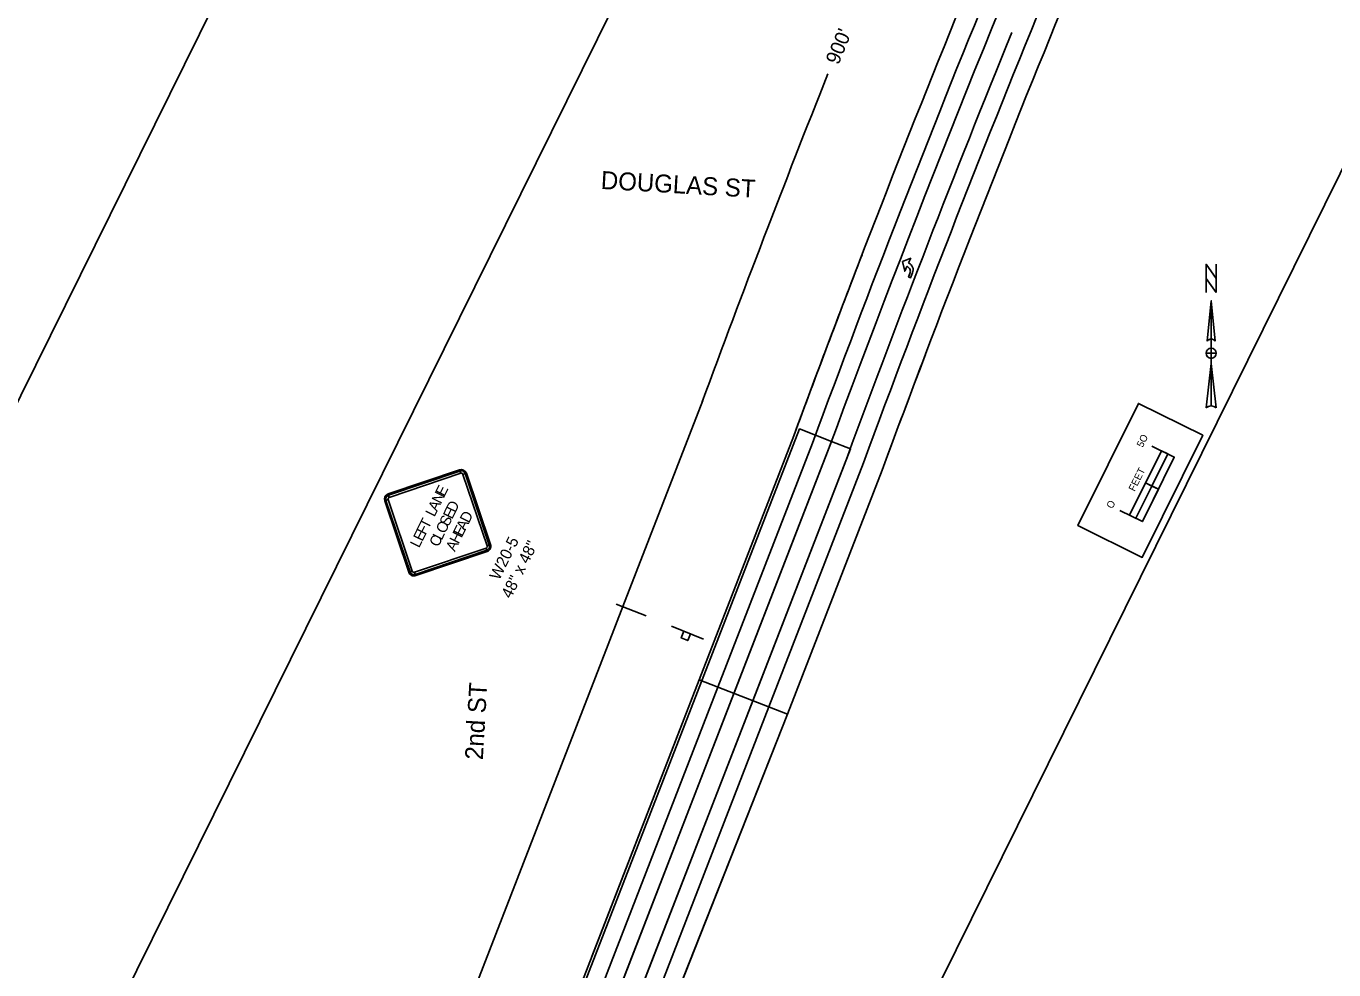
# Model space of a CAD drawing. Extents: x 14104283 to 14129344, y 8637090 to 8673339.
# Drawn here: x 14119504 to 14120414, y 8670301 to 8670958 of the extents above; entities that cross this region are included whole.
import ezdxf

# ---------------------------------------------------------------- set-up
doc = ezdxf.new("R2010")
doc.units = 0
for name, color, linetype in [('Cell', 7, 'Continuous'), ('Default', 7, 'Continuous'), ('dsnCellsNorthArrow', 7, 'Continuous'), ('dsnCellsScaleBlock', 7, 'Continuous'), ('dsnNonPlotable', 7, 'Continuous'), ('dsnPaintExistingBrokenLaneLineWhite', 7, 'Continuous'), ('dsnPaintExistingEdgeLineRightWhite', 7, 'Continuous'), ('dsnPaintExistingNoPassingYellow', 7, 'Continuous'), ('dsnPaintExistingSymbolWhite', 7, 'Continuous'), ('dsnShadingPaved', 7, 'Continuous'), ('dsnStdLabel', 7, 'Continuous'), ('dsnTextOverlapEven', 7, 'Continuous'), ('dsnTextOverlapOdd', 7, 'Continuous')]:
    doc.layers.add(name, color=color, linetype=linetype)

msp = doc.modelspace()

# ---------------------------------------------------------------- linework, layer by layer
at = {"layer": 'Cell'}
for p, q in [((14120117.97, 8670793.22), (14120118.14, 8670793.15)), ((14120117.15, 8670790.72), (14120116.85, 8670790.83)), ((14119805.41, 8670649.2), (14119755.68, 8670632.38)), ((14119805.71, 8670648.31), (14119806.21, 8670646.84)), ((14119807.8, 8670646.05), (14119809.28, 8670646.55)), ((14119826.99, 8670597.12), (14119810.16, 8670646.85)), ((14119753.33, 8670627.62), (14119770.15, 8670577.89)), ((14119754.22, 8670627.93), (14119755.7, 8670628.43)), ((14119756.48, 8670630.01), (14119755.98, 8670631.49)), ((14119774.91, 8670575.54), (14119824.64, 8670592.37)), ((14119823.84, 8670594.74), (14119824.34, 8670593.26)), ((14119826.1, 8670596.82), (14119824.62, 8670596.32)), ((14119772.52, 8670578.69), (14119771.04, 8670578.19)), ((14119774.61, 8670576.43), (14119774.11, 8670577.91)), ((14119952.85, 8670540.35), (14119975.12, 8670531.39))]:
    msp.add_line(p, q, dxfattribs=at)
for points in [[(14120113.8, 8670794.36), (14120119.54, 8670796.55), (14120117.97, 8670793.22)], [(14120113.8, 8670794.36), (14120119.54, 8670796.55), (14120117.97, 8670793.22)], [(14120116.85, 8670790.83), (14120115.29, 8670787.5), (14120113.8, 8670794.36)], [(14120116.85, 8670790.83), (14120115.29, 8670787.5), (14120113.8, 8670794.36)], [(14120117.97, 8670793.22), (14120118.14, 8670793.15)], [(14120117.15, 8670790.72), (14120116.85, 8670790.83)], [(14120120.76, 8670786.39), (14120119.36, 8670782.99), (14120117.98, 8670783.56), (14120118.97, 8670785.99)], [(14120120.76, 8670786.39), (14120119.36, 8670782.99), (14120117.98, 8670783.56), (14120118.97, 8670785.99)], [(14119966.14, 8670534.92), (14119961.58, 8670536.75), (14119959.75, 8670532.19), (14119964.31, 8670530.36), (14119966.14, 8670534.92)]]:
    msp.add_lwpolyline(points, dxfattribs=at)
for points in [[(14119805.71, 8670648.31), (14119755.98, 8670631.49), (14119756.48, 8670630.01), (14119806.21, 8670646.84), (14119805.71, 8670648.31)], [(14119826.1, 8670596.82), (14119809.28, 8670646.55), (14119807.8, 8670646.05), (14119824.62, 8670596.32), (14119826.1, 8670596.82)], [(14119754.22, 8670627.93), (14119771.04, 8670578.19), (14119772.52, 8670578.69), (14119755.7, 8670628.43), (14119754.22, 8670627.93)], [(14119774.61, 8670576.43), (14119824.34, 8670593.26), (14119823.84, 8670594.74), (14119774.11, 8670577.91), (14119774.61, 8670576.43)], [(14119966.14, 8670534.92), (14119961.58, 8670536.75), (14119959.75, 8670532.19), (14119964.31, 8670530.36)]]:
    msp.add_lwpolyline(points, close=True, dxfattribs=at)
for centre, radius, start, end in [((14119806.61, 8670645.65), 3.75, 18.69133, 108.69097), ((14119806.61, 8670645.65), 2.81, 18.69133, 108.69097), ((14119806.61, 8670645.65), 1.25, 18.69133, 108.69097), ((14119756.88, 8670628.83), 3.75, 108.69116, 198.69091), ((14119756.88, 8670628.83), 2.81, 108.69116, 198.69091), ((14119756.88, 8670628.83), 1.25, 108.69116, 198.69091), ((14119823.44, 8670595.92), 1.25, 288.69112, 18.69133), ((14119823.44, 8670595.92), 2.81, 288.69112, 18.69133), ((14119823.44, 8670595.92), 3.75, 288.69112, 18.69133), ((14119773.71, 8670579.1), 3.75, 198.69091, 288.69112), ((14119773.71, 8670579.1), 2.81, 198.69091, 288.69112), ((14119773.71, 8670579.1), 1.25, 198.69091, 288.69112)]:
    msp.add_arc(centre, radius, start, end, dxfattribs=at)
for centre, major_axis in [((14120116.15, 8670788.28), (-2, -4.86)), ((14120116.15, 8670788.28), (-2, -4.86)), ((14120115.75, 8670787.31), (-1.4, -3.4)), ((14120115.75, 8670787.31), (-1.4, -3.4))]:
    msp.add_ellipse(centre, major_axis=major_axis, ratio=0.9474, start_param=1.570796, end_param=3.141593, dxfattribs=at)
at = {"layer": 'Default'}
for p, q in [((14119972.19, 8670502.91), (14120038.08, 8670672.89)), ((14120099.62, 8670649.04), (14120033.72, 8670479.06)), ((14120033.72, 8670479.06), (14119972.19, 8670502.91))]:
    msp.add_line(p, q, dxfattribs=at)
msp.add_lwpolyline([(14119861.3, 8670216.88), (14119920.98, 8670193.76), (14120033.72, 8670479.06), (14119972.19, 8670502.91)], close=True, dxfattribs=at)
for centre in [(14129121.85, 8667322.17), (14129183.39, 8667298.31)]:
    msp.add_arc(centre, 9682.06, 155.679047, 159.752527, dxfattribs=at)
at = {"layer": 'dsnCellsNorthArrow'}
for p, q in [((14120328.64, 8670766.96), (14120331.45, 8670738.79)), ((14120328.64, 8670766.96), (14120328.64, 8670693.71)), ((14120325.82, 8670738.79), (14120325.82, 8670738.79)), ((14120325.93, 8670739.05), (14120326.45, 8670739.63)), ((14120325.12, 8670692.3), (14120328.64, 8670723.29)), ((14120328.64, 8670726.82), (14120328.64, 8670726.81))]:
    msp.add_line(p, q, dxfattribs=at)
msp.add_lwpolyline([(14120332.16, 8670772.59), (14120325.12, 8670782.45), (14120325.12, 8670792.31), (14120332.16, 8670782.45)], close=True, dxfattribs=at)
for points in [[(14120325.12, 8670772.59), (14120325.12, 8670792.31), (14120332.16, 8670782.45), (14120332.16, 8670792.31)], [(14120325.82, 8670738.79), (14120328.64, 8670766.96), (14120328.64, 8670740.2)], [(14120328.64, 8670726.81), (14120328.64, 8670730.34), (14120325.12, 8670730.34)], [(14120332.16, 8670730.34), (14120328.64, 8670730.34), (14120328.64, 8670733.86)], [(14120328.64, 8670693.71), (14120328.64, 8670723.29), (14120332.16, 8670692.31)]]:
    msp.add_lwpolyline(points, dxfattribs=at)
for centre, radius, start, end in [((14120328.64, 8670736.67), 3.52, 90.02039, 143.12574), ((14120328.64, 8670736.68), 3.52, 36.84806, 90.02184), ((14120328.64, 8670730.34), 3.52, 90, 180), ((14120328.64, 8670730.34), 3.52, 180, 270), ((14120328.64, 8670730.34), 3.52, 0, 90), ((14120328.64, 8670730.34), 3.52, 270, 360), ((14120328.64, 8670688.61), 5.1, 89.98939, 133.61895), ((14120328.64, 8670688.61), 5.11, 46.40206, 90.00064)]:
    msp.add_arc(centre, radius, start, end, dxfattribs=at)
at = {"layer": 'dsnCellsScaleBlock'}
msp.add_line((14120291.87, 8670635.63), (14120282.9, 8670640.06), dxfattribs=at)
msp.add_line((14120291.87, 8670635.63), (14120282.9, 8670640.06), dxfattribs=at)
for points in [[(14120235.85, 8670610.33), (14120277.96, 8670695.49), (14120322.78, 8670673.33), (14120280.67, 8670588.17)], [(14120280.67, 8670588.17), (14120235.85, 8670610.33), (14120277.96, 8670695.49), (14120322.78, 8670673.33)], [(14120287.35, 8670637.86), (14120298.43, 8670660.27), (14120293.98, 8670662.47), (14120282.9, 8670640.06)], [(14120280.78, 8670613.22), (14120291.87, 8670635.63), (14120287.35, 8670637.86), (14120276.27, 8670615.45)]]:
    msp.add_lwpolyline(points, close=True, dxfattribs=at)
for points in [[(14120265.1, 8670620.97), (14120280.78, 8670613.22), (14120302.95, 8670658.04), (14120287.26, 8670665.79)], [(14120271.82, 8670617.65), (14120293.98, 8670662.47)]]:
    msp.add_lwpolyline(points, dxfattribs=at)
at = {"layer": 'dsnNonPlotable'}
for points in [[(14119282.05, 8670260.59), (14119976.78, 8671665.73), (14120882.16, 8671218.09), (14120187.43, 8669812.95)], [(14119506.15, 8670149.79), (14120200.88, 8671554.92), (14120653.57, 8671331.1), (14119958.84, 8669925.97)]]:
    msp.add_lwpolyline(points, close=True, dxfattribs=at)
at = {"layer": 'dsnPaintExistingBrokenLaneLineWhite'}
for p, q in [((14119985.24, 8670497.85), (14120051.13, 8670667.83)), ((14120020.67, 8670484.12), (14120086.56, 8670654.1)), ((14119874.41, 8670211.95), (14119985.24, 8670497.85)), ((14119909.84, 8670198.21), (14120020.67, 8670484.12))]:
    msp.add_line(p, q, dxfattribs=at)
for centre in [(14129134.9, 8667317.11), (14129170.33, 8667303.37)]:
    msp.add_arc(centre, 9682.06, 155.679047, 159.752527, dxfattribs=at)
at = {"layer": 'dsnPaintExistingEdgeLineRightWhite'}
for p, q in [((14120038.08, 8670672.89), (14119972.19, 8670502.91)), ((14120033.72, 8670479.06), (14120099.62, 8670649.04)), ((14119972.19, 8670502.91), (14119897.54, 8670310.36)), ((14119920.98, 8670193.76), (14120033.72, 8670479.06))]:
    msp.add_line(p, q, dxfattribs=at)
for centre, start in [((14129121.85, 8667322.17), 158.955067), ((14129183.39, 8667298.31), 159.24373)]:
    msp.add_arc(centre, 9682.06, start, 159.752527, dxfattribs=at)
at = {"layer": 'dsnPaintExistingNoPassingYellow'}
for p, q in [((14120062.32, 8670663.5), (14119996.43, 8670493.52)), ((14120009.48, 8670488.46), (14120075.37, 8670658.44)), ((14119996.43, 8670493.52), (14119885.6, 8670207.61)), ((14119898.65, 8670202.55), (14120009.48, 8670488.46))]:
    msp.add_line(p, q, dxfattribs=at)
for centre, start in [((14129146.09, 8667312.77), 156.77428), ((14129159.14, 8667307.71), 157.878476)]:
    msp.add_arc(centre, 9682.06, start, 159.752527, dxfattribs=at)
at = {"layer": 'dsnPaintExistingSymbolWhite'}
for p, q in [((14120117.97, 8670793.22), (14120118.14, 8670793.15)), ((14120117.15, 8670790.72), (14120116.85, 8670790.83))]:
    msp.add_line(p, q, dxfattribs=at)
for points in [[(14120113.8, 8670794.36), (14120119.54, 8670796.55), (14120117.97, 8670793.22)], [(14120113.8, 8670794.36), (14120119.54, 8670796.55), (14120117.97, 8670793.22)], [(14120116.85, 8670790.83), (14120115.29, 8670787.5), (14120113.8, 8670794.36)], [(14120116.85, 8670790.83), (14120115.29, 8670787.5), (14120113.8, 8670794.36)], [(14120117.97, 8670793.22), (14120118.14, 8670793.15)], [(14120117.15, 8670790.72), (14120116.85, 8670790.83)], [(14120120.76, 8670786.39), (14120119.36, 8670782.99), (14120117.98, 8670783.56), (14120118.97, 8670785.99)], [(14120120.76, 8670786.39), (14120119.36, 8670782.99), (14120117.98, 8670783.56), (14120118.97, 8670785.99)]]:
    msp.add_lwpolyline(points, dxfattribs=at)
for centre, major_axis in [((14120116.15, 8670788.28), (-2, -4.86)), ((14120116.15, 8670788.28), (-2, -4.86)), ((14120115.75, 8670787.31), (-1.4, -3.4)), ((14120115.75, 8670787.31), (-1.4, -3.4))]:
    msp.add_ellipse(centre, major_axis=major_axis, ratio=0.9474, start_param=1.570796, end_param=3.141593, dxfattribs=at)
at = {"layer": 'dsnShadingPaved'}
for points in [[(14119863.22, 8670216.29), (14120042.07, 8670677.65), (14120064.44, 8670668.98), (14119885.6, 8670207.61)], [(14119885.6, 8670207.61), (14120064.44, 8670668.98), (14120077.5, 8670663.92), (14119922.69, 8670264.56), (14119945.07, 8670255.89), (14119945.07, 8670255.89), (14119921.03, 8670193.88)]]:
    msp.add_lwpolyline(points, dxfattribs=at)
at = {"layer": 'dsnStdLabel'}
for p, q in [((14119919.04, 8670553.95), (14119974.67, 8670697.47)), ((14119914.35, 8670555.77), (14119935.33, 8670547.64)), ((14119908.76, 8670527.51), (14119919.01, 8670553.96)), ((14119807.69, 8670266.77), (14119908.76, 8670527.51))]:
    msp.add_line(p, q, dxfattribs=at)
msp.add_arc((14129121.85, 8667322.17), 9750.06, 158.315185, 159.752527, dxfattribs=at)

# ---------------------------------------------------------------- texts
at = {"layer": 'Cell'}
for s, height, p in [('E', 7.5, (14119794.94, 8670630.15)), ('N', 7.5, (14119792.42, 8670625.06)), ('L', 7.5, (14119787.93, 8670615.98)), ('A', 7.5, (14119789.78, 8670619.72)), ('E', 7.5, (14119800.22, 8670614.4)), ('D', 7.5, (14119802.45, 8670618.89)), ('D', 7.5, (14119811.94, 8670611.66)), ('F', 7.5, (14119781.72, 8670603.42)), ('T', 7.5, (14119783.76, 8670607.54)), ('O', 7.5, (14119795.22, 8670604.28)), ('S', 7.5, (14119797.71, 8670609.3)), ('E', 7.5, (14119807.28, 8670602.22)), ('A', 7.5, (14119809.31, 8670606.34)), ('E', 7.5, (14119779.5, 8670598.92)), ('C', 7.5, (14119790.62, 8670594.97)), ('L', 7.5, (14119793, 8670599.79)), ('H', 7.5, (14119804.77, 8670597.14)), ('W20-5', 8, (14119832.98, 8670571.79)), ('48" x 48"', 8, (14119841.17, 8670559.02)), ('L', 7.5, (14119777.27, 8670594.42)), ('A', 7.5, (14119802.13, 8670591.82))]:
    msp.add_text(s, height=height, rotation=63.69117, dxfattribs=at).set_placement(p)
at = {"layer": 'dsnCellsScaleBlock'}
for s, p in [('5O', (14120280.97, 8670664.36)), ('FEET', (14120275.34, 8670633.79)), ('O', (14120259.89, 8670621.73))]:
    msp.add_text(s, height=5, rotation=63.69117, dxfattribs=at).set_placement(p)
at = {"layer": 'dsnStdLabel'}
msp.add_text("900'", height=10, rotation=67.60023, dxfattribs=at).set_placement((14120069.14, 8670930.68))
at = {"layer": 'dsnTextOverlapEven'}
msp.add_text('2nd ST', height=12.5, rotation=86.69117, dxfattribs=at).set_placement((14119821.61, 8670446.97))
at = {"layer": 'dsnTextOverlapOdd'}
msp.add_text('DOUGLAS ST', height=12.5, rotation=356.69117, dxfattribs=at).set_placement((14119903.52, 8670844.82))

doc.saveas('drawing.dxf')
